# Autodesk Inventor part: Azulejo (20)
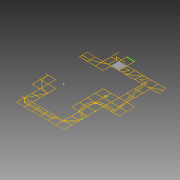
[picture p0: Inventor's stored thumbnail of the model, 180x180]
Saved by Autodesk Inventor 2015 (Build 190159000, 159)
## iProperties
Created: 2015-04
Part Number: Azulejo (20)
Material: Genérico
Document SubType Name: Modeling
Designer: Felipe
Density: 1 g/cm^3
Appearance: Padrão
Author: Felipe
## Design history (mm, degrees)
sketch "Sketch1"
  geometry: L1 (-1510, -7490)-(-1510, -6010); L2 (992.445, 7510)-(992.445, 8990); L3 (1012.445, 7510)-(1012.445, 8990); L4 (-3010, -1490)-(-3010, -10); L5 (-1510, 7490)-(-2990, 7490); L6 (-2990, 10)-(-1510, 10); L7 (-1510, -10)-(-2990, -10); L8 (-1510, -1490)-(-1510, -10); L9 (-10, 9010)-(-10, 10490); L10 (-10, 7510)-(-10, 8990); L11 (-10, 7490)-(-1490, 7490); L12 (-1490, 6010)-(-10, 6010); L13 (-10, 5990)-(-1490, 5990); L14 (-1490, -10)-(-1490, -1490); L15 (-1490, -1490)-(-10, -1490); L16 (-10, -1510)-(-1490, -1510); L17 (-10, -2990)-(-10, -1510); L18 (-10, -5990)-(-10, -4510); L19 (-1490, -7490)-(-10, -7490); L20 (10, 8990)-(10, 7510); L21 (1490, 7510)-(1490, 8990); L22 (10, 6010)-(1490, 6010); L23 (1490, 6010)-(1490, 7490); L24 (1490, 5990)-(10, 5990); L25 (4490, -6010)-(3010, -6010); L26 (10, -1510)-(10, -2990); L27 (10, -3010)-(10, -4490); L28 (10, -4510)-(10, -5990); L29 (10, -5990)-(1490, -5990); L30 (1490, -6010)-(10, -6010); L31 (10, -7490)-(1490, -7490); L32 (2990, 9010)-(2990, 10490); L33 (1510, 8990)-(1510, 7510); L34 (1510, 7510)-(2990, 7510); L35 (2990, 7490)-(1510, 7490); L36 (1510, 7490)-(1510, 6010); L37 (1510, -5990)-(2990, -5990); L38 (2990, -6010)-(1510, -6010); L39 (1510, -7490)-(2990, -7490); L40 (3010, 10490)-(3010, 9010); L41 (3010, 9010)-(4490, 9010); L42 (4490, 8990)-(3010, 8990); L43 (4490, 7490)-(3010, 7490); L44 (4490, 1510)-(4490, 2990); L45 (4490, 10)-(4490, 1490); L46 (4490, -1490)-(4490, -10); L47 (4490, -2990)-(4490, -1510); L48 (3010, -5990)-(4490, -5990); L49 (3010, -7490)-(4490, -7490); L50 (4510, 9010)-(5990, 9010); L51 (5990, 8990)-(4510, 8990); L52 (4510, 7510)-(5990, 7510); L53 (5990, 7490)-(4510, 7490); L54 (4510, 3010)-(5990, 3010); L55 (5990, 2990)-(4510, 2990); L56 (4510, 2990)-(4510, 1510); L57 (4510, 1510)-(5990, 1510); L58 (5990, 1510)-(5990, 1740.185); L59 (5990, 1760.2)-(5990, 2259.8); L60 (5990, 2279.815)-(5990, 2990); L61 (5990, 1490)-(4510, 1490); L62 (4510, 1490)-(4510, 10); L63 (4510, 10)-(5990, 10); L64 (5990, 10)-(5990, 1490)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; A1 r 250 centre (6000, 2010) between (5990, 2259.8) and (5990, 1760.2); A2 r 250 centre (6000, 2010) between (6010, 1760.2) and (6010, 2259.8); A3 r 270 centre (6000, 2010) between (5990, 2279.815) and (5990, 1740.185); A4 r 270 centre (6000, 2010) between (6010, 1740.185) and (6010, 2279.815); A5 r 3010.017 centre (0, 0) between (-1490, -2615.358) and (-346.554, -2990); A6 r 2990.017 centre (0, 0) between (-1490, -2592.316) and (-10, -2990); A7 r 3010.017 centre (0, 0) between (-2603.863, -1510) and (-1510, -2603.863); A8 r 2990.017 centre (0, 0) between (-2580.717, -1510) and (-1510, -2580.717); A9 r 3010.017 centre (0, 0) between (-2990, -346.554) and (-2615.358, -1490); A10 r 2990.017 centre (0, 0) between (-2990, -10) and (-2592.316, -1490); A11 r 2131.367 centre (7500, -1500) between (7490, 631.344) and (6010, 24.017); A12 r 2131.367 centre (7500, -1500) between (5975.983, -10) and (5368.656, -1490); A13 r 2131.367 centre (7500, -1500) between (5368.656, -1510) and (5975.983, -2990); A14 r 2131.367 centre (7500, -1500) between (6010, -3024.017) and (7190, -3608.703); A15 r 1831.367 centre (7500, -1500) between (7490.321, 331.342) and (6463.753, 10); A16 r 1831.367 centre (7500, -1500) between (6435.196, -10) and (6010, -435.196); A17 r 1831.367 centre (7500, -1500) between (5990, -463.753) and (5668.66, -1490); A18 r 1831.367 centre (7500, -1500) between (5668.66, -1510) and (5990, -2536.247); A19 r 1831.367 centre (7500, -1500) between (6010, -2564.804) and (6435.196, -2990); A20 r 1831.367 centre (7500, -1500) between (6463.753, -3010) and (7490, -3331.34); A21 r 2111.367 centre (7500, -1500) between (7490.047, 611.344) and (6024.272, 10); A22 r 2111.367 centre (7500, -1500) between (5990, -24.272) and (5388.656, -1490); A23 r 2111.367 centre (7500, -1500) between (5388.656, -1510) and (5990, -2975.728); A24 r 2111.367 centre (7500, -1500) between (6024.272, -3010) and (7210, -3591.357); A25 r 1811.367 centre (7500, -1500) between (7490.374, 311.342) and (6499.524, 10); A26 r 1811.367 centre (7500, -1500) between (6469.975, -10) and (6010, -469.975); A27 r 1811.367 centre (7500, -1500) between (5990, -499.524) and (5688.66, -1490); A28 r 1811.367 centre (7500, -1500) between (5688.66, -1510) and (5990, -2500.476); A29 r 1811.367 centre (7500, -1500) between (6010, -2530.025) and (6469.975, -2990); A30 r 1811.367 centre (7500, -1500) between (6499.524, -3010) and (7490, -3311.34); A31 r 449.871 centre (7499.449, -4060.672) between (7510, -4510.419) and (7521.546, -4510); 5 further points
  constraints: 1042 end point, 64 point on circle, 31 centre point, 13 point on line, 1 horizontal, 1 other
extrude "Extrusion1" new body sketch "Sketch1" distance "d0" = 60; taper "d1" = 0 deg
extrude "Extrusion2" new body sketch "Sketch1" distance "d2" = 60; taper "d3" = 0 deg
body "Solid1"
body "Solid2"
